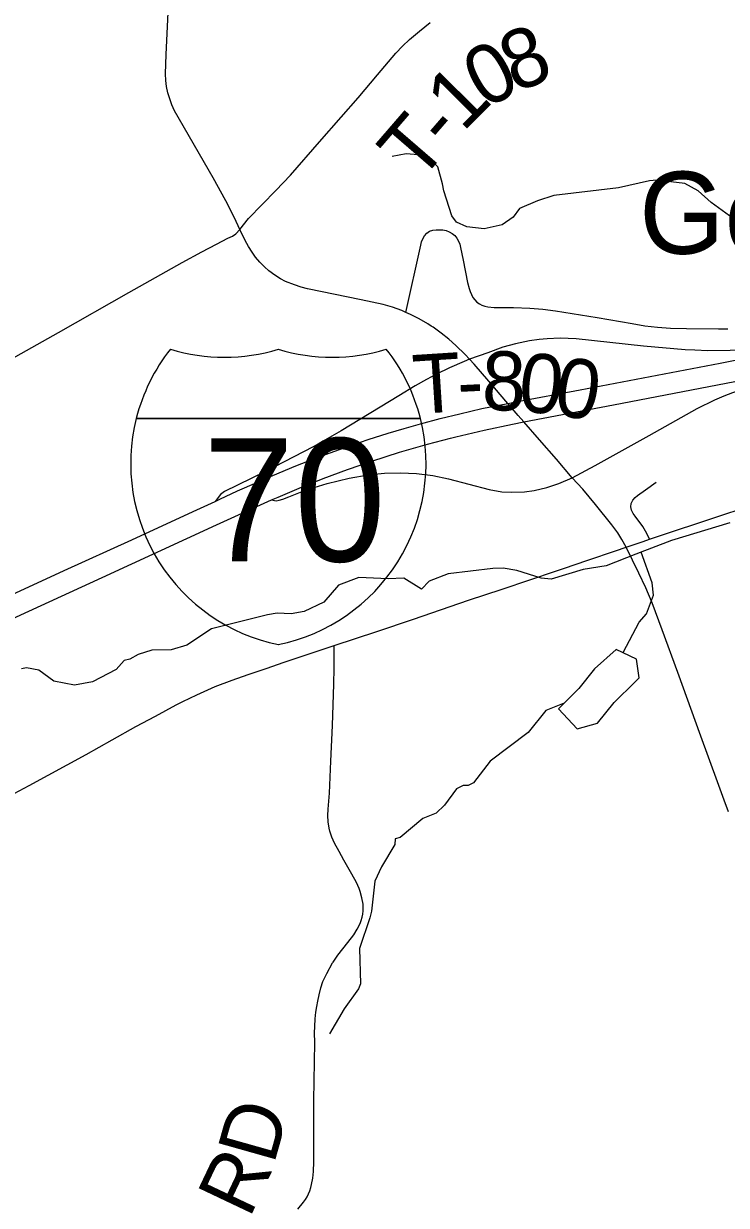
# Model space of a CAD drawing. Extents: x 0 to 34, y 0 to 22.
# Drawn here: x 5.879 to 6.555, y 16.504 to 17.641 of the extents above; entities that cross this region are included whole.
import ezdxf

# ---------------------------------------------------------------- set-up
doc = ezdxf.new("R2010")
doc.units = 0
for name, color, linetype in [('GM_X_County_Road', 7, 'Continuous'), ('GM_X_County_Road_Text', 7, 'Continuous'), ('GM_X_Interchange_Ramps', 7, 'Continuous'), ('GM_X_Interstate_Location', 7, 'Continuous'), ('GM_X_Interstate_Route', 7, 'Continuous'), ('GM_X_Interstate_Shield', 7, 'Continuous'), ('GM_X_Minor_Lake', 7, 'Continuous'), ('GM_X_Minor_River', 7, 'Continuous'), ('GM_X_Township_Road', 7, 'Continuous'), ('GM_X_Township_Road_Text', 7, 'Continuous'), ('GM_X_Unincorporated_Text', 7, 'Continuous'), ('GM_X_US_Route', 7, 'Continuous')]:
    doc.layers.add(name, color=color, linetype=linetype)

msp = doc.modelspace()

# ---------------------------------------------------------------- linework, layer by layer
at = {"layer": 'GM_X_County_Road'}
msp.add_line((6.5568, 16.8829), (6.5527, 16.8941), dxfattribs=at)
for points in [[(6.0868, 17.4429), (6.0816, 17.454), (6.0731, 17.4704), (6.061, 17.4925), (6.024, 17.5571), (6.0214, 17.5627), (6.0193, 17.5684), (6.0175, 17.5743), (6.0163, 17.5803), (6.0155, 17.5863), (6.0152, 17.5925), (6.0157, 17.6111), (6.0186, 17.672), (6.0235, 17.762)], [(5.6309, 17.1975), (5.6373, 17.2025), (5.6495, 17.2114), (5.6571, 17.2161), (5.6635, 17.2194), (5.6722, 17.2229), (5.7007, 17.2329), (5.7281, 17.2426), (5.7393, 17.247), (5.7476, 17.2511), (5.7585, 17.257), (5.7719, 17.2647), (5.8149, 17.2893), (5.8611, 17.3149), (5.9124, 17.3439), (5.9799, 17.3822), (6.0313, 17.4112), (6.0502, 17.4215), (6.0641, 17.4289), (6.0753, 17.4344), (6.0797, 17.4363), (6.0828, 17.4387), (6.0868, 17.4429)], [(6.2465, 17.3631), (6.2424, 17.3649), (6.2336, 17.3681), (6.2245, 17.3706), (6.2033, 17.3753), (6.1517, 17.3857), (6.1457, 17.3874), (6.1392, 17.3895), (6.1306, 17.3929), (6.1258, 17.3954), (6.1203, 17.3989), (6.1147, 17.4032), (6.1104, 17.4071), (6.1058, 17.4113), (6.1018, 17.4162), (6.0985, 17.4211), (6.0951, 17.4266), (6.0917, 17.4324), (6.0868, 17.4429)], [(6.2709, 17.35), (6.2675, 17.3522), (6.2593, 17.3568), (6.251, 17.3612), (6.2465, 17.3631)], [(6.3077, 17.3182), (6.3035, 17.3226), (6.2946, 17.3313), (6.2876, 17.3375), (6.2803, 17.3433), (6.2727, 17.3488), (6.2709, 17.35)], [(6.4063, 17.2039), (6.3914, 17.2219), (6.375, 17.2406), (6.3599, 17.2578), (6.3545, 17.2639), (6.3445, 17.2756), (6.3262, 17.297), (6.312, 17.3135), (6.3077, 17.3182)], [(6.4583, 17.1372), (6.4543, 17.1446), (6.4502, 17.1512), (6.4446, 17.1588), (6.4288, 17.1785), (6.4166, 17.193), (6.4063, 17.2039)], [(6.5527, 16.8941), (6.5462, 16.9118), (6.5302, 16.9555), (6.5081, 17.0169), (6.4931, 17.0577), (6.4832, 17.0838), (6.4772, 17.0982), (6.4705, 17.1122), (6.4583, 17.1372)], [(6.1764, 16.7384), (6.1811, 16.7451), (6.1906, 16.7572), (6.1962, 16.7646), (6.1996, 16.7699), (6.2024, 16.7754), (6.2035, 16.7784), (6.2044, 16.7814), (6.205, 16.7845), (6.2053, 16.7876), (6.2054, 16.7907), (6.2052, 16.7939), (6.2042, 16.8001), (6.2025, 16.8062), (6.2014, 16.8091), (6.1989, 16.8148), (6.1945, 16.823), (6.1868, 16.8365), (6.1821, 16.8446), (6.1778, 16.8527), (6.1753, 16.8584), (6.1733, 16.8642), (6.1726, 16.8671), (6.1717, 16.8732), (6.1715, 16.8793), (6.1718, 16.8855), (6.1728, 16.9009), (6.1735, 16.9163), (6.1742, 16.9317), (6.1758, 16.9657), (6.177, 17.0057), (6.1774, 17.0211), (6.1775, 17.0429)], [(6.1425, 16.5007), (6.148, 16.5074), (6.1498, 16.51), (6.1514, 16.5127), (6.1539, 16.5184), (6.1549, 16.5214), (6.1557, 16.5244), (6.1568, 16.5306), (6.1575, 16.5368), (6.1579, 16.5461), (6.1578, 16.5678), (6.1579, 16.5834), (6.1578, 16.6051), (6.1584, 16.6423), (6.1587, 16.6609), (6.1586, 16.6702), (6.1588, 16.6763), (6.1592, 16.6839), (6.1598, 16.6901), (6.1607, 16.6956), (6.1618, 16.7009), (6.1629, 16.7069), (6.1646, 16.7136), (6.1666, 16.7197), (6.1703, 16.7274), (6.1758, 16.7376), (6.1764, 16.7384)]]:
    msp.add_lwpolyline(points, dxfattribs=at)
at = {"layer": 'GM_X_Interchange_Ramps'}
for points in [[(6.638, 17.332), (6.6278, 17.3335), (6.6194, 17.3334), (6.5993, 17.3304), (6.5832, 17.3283), (6.5694, 17.327), (6.5585, 17.3265), (6.5368, 17.3262), (6.5244, 17.3268), (6.5151, 17.3271), (6.475, 17.3308), (6.4102, 17.3376), (6.3948, 17.3382), (6.3824, 17.3378), (6.3748, 17.3371), (6.3654, 17.3359), (6.3518, 17.333), (6.3398, 17.3297), (6.3253, 17.3243), (6.3077, 17.3182)], [(6.4063, 17.2039), (6.4286, 17.2158), (6.4804, 17.2447), (6.5267, 17.2707), (6.5435, 17.279), (6.5525, 17.283), (6.5608, 17.2861), (6.5786, 17.292), (6.6029, 17.2981), (6.6461, 17.3071), (6.6703, 17.312), (6.6778, 17.315), (6.6856, 17.3202)], [(6.3077, 17.3182), (6.3024, 17.3158), (6.2883, 17.3097), (6.276, 17.3038), (6.2662, 17.2985), (6.2554, 17.2925), (6.2395, 17.283), (6.1841, 17.2491), (6.1573, 17.2338), (6.1106, 17.2097), (6.0719, 17.191), (6.0682, 17.188), (6.063, 17.1814)], [(6.1173, 17.1828), (6.1216, 17.182), (6.1245, 17.1825), (6.1281, 17.1834), (6.1337, 17.1857), (6.1499, 17.1921), (6.1707, 17.1985), (6.1919, 17.2038), (6.2102, 17.2069), (6.2257, 17.2084), (6.2413, 17.2088), (6.2568, 17.2081), (6.2722, 17.2062), (6.2875, 17.2032), (6.3265, 17.1928), (6.3388, 17.1907), (6.3481, 17.1901), (6.3605, 17.1905), (6.3698, 17.1917), (6.3819, 17.1946), (6.3936, 17.1986), (6.4063, 17.2039)]]:
    msp.add_lwpolyline(points, dxfattribs=at)
at = {"layer": 'GM_X_Interstate_Route'}
for points in [[(6.4461, 17.2744), (6.5961, 17.303), (6.6856, 17.3202), (6.7151, 17.3259), (6.8371, 17.3495), (6.8976, 17.361)], [(6.063, 17.1814), (6.0673, 17.1834), (6.0846, 17.1914), (6.103, 17.1996), (6.1183, 17.2063), (6.1405, 17.2156), (6.1638, 17.2247), (6.1879, 17.2333), (6.2102, 17.2409), (6.2295, 17.2469), (6.2449, 17.2514), (6.2605, 17.2561), (6.2793, 17.2611), (6.2984, 17.2656), (6.3194, 17.2706), (6.3445, 17.2756), (6.3522, 17.2772), (6.4142, 17.2888), (6.5486, 17.3144), (6.638, 17.332)], [(6.2895, 17.2422), (6.2944, 17.2434), (6.3216, 17.2499), (6.349, 17.2557), (6.3599, 17.2578), (6.4344, 17.2721), (6.4461, 17.2744)], [(6.1173, 17.1828), (6.1236, 17.1855), (6.1438, 17.1942), (6.1669, 17.2035), (6.1902, 17.2121), (6.2137, 17.2202), (6.2404, 17.2286), (6.2673, 17.2363), (6.2895, 17.2422)], [(4.7609, 16.6592), (4.7838, 16.6653), (4.8529, 16.6836), (5.0932, 16.7471), (5.132, 16.758), (5.1647, 16.7679), (5.2061, 16.7812), (5.2414, 16.7931), (5.2823, 16.8079), (5.3288, 16.8255), (5.3663, 16.8405), (5.4006, 16.855), (5.4545, 16.879), (5.5249, 16.9113), (5.6013, 16.9464), (5.9542, 17.1082), (6.0643, 17.1589), (6.1173, 17.1828)], [(5.7653, 17.0446), (5.9177, 17.1148), (5.9827, 17.1444), (6.0419, 17.1717), (6.063, 17.1814)]]:
    msp.add_lwpolyline(points, dxfattribs=at)
at = {"layer": 'GM_X_Interstate_Shield'}
for p, q in [((5.9871, 17.2612), (6.2604, 17.2612)), ((6.2604, 17.2612), (5.9871, 17.2612)), ((6.2604, 17.2612), (5.9871, 17.2612))]:
    msp.add_line(p, q, dxfattribs=at)
for centre, start, end in [((6.1593, 17.2177), 141.669, 165.8066), ((6.0719, 17.4976), 253.0091, 286.9909), ((6.1756, 17.4976), 253.0091, 286.9909), ((6.0882, 17.2177), 14.1934, 38.331), ((6.1593, 17.2177), 165.8066, 258.463), ((6.0882, 17.2177), 281.537, 14.1934)]:
    msp.add_arc(centre, 0.1776, start, end, dxfattribs=at)
at = {"layer": 'GM_X_Minor_Lake'}
for points in [[(6.4709, 17.0118), (6.4683, 17.0296), (6.4486, 17.0391), (6.4278, 17.0205), (6.4127, 17.0015), (6.3934, 16.9818)], [(6.4709, 17.0118), (6.4683, 17.0296), (6.4486, 17.0391), (6.4278, 17.0205), (6.4127, 17.0015), (6.3934, 16.9818), (6.4111, 16.9625), (6.4308, 16.9681), (6.4467, 16.9879), (6.4671, 17.008), (6.4709, 17.0118)], [(6.3934, 16.9818), (6.4111, 16.9625), (6.4308, 16.9681), (6.4467, 16.9879), (6.4671, 17.008), (6.4709, 17.0118)]]:
    msp.add_lwpolyline(points, dxfattribs=at)
at = {"layer": 'GM_X_Minor_River'}
for points in [[(6.5682, 17.4483), (6.5402, 17.4687), (6.5276, 17.48), (6.5147, 17.4872), (6.4878, 17.4904), (6.4807, 17.4896), (6.4508, 17.483), (6.3888, 17.4755), (6.3729, 17.4705), (6.3556, 17.4631), (6.3496, 17.4548), (6.339, 17.4475), (6.3216, 17.4436), (6.305, 17.4454), (6.2951, 17.4499), (6.2906, 17.456), (6.2829, 17.4802), (6.2817, 17.4867), (6.2771, 17.503), (6.2725, 17.5083), (6.2581, 17.5146), (6.2468, 17.5157), (6.2331, 17.513)], [(6.5579, 17.1609), (6.502, 17.1439), (6.4677, 17.1305), (6.439, 17.1193), (6.4171, 17.1158), (6.3861, 17.1065), (6.3766, 17.1076), (6.3531, 17.115), (6.3399, 17.1173), (6.3301, 17.1168), (6.287, 17.1117), (6.2688, 17.1047), (6.2613, 17.0971), (6.2446, 17.1076), (6.2295, 17.1068), (6.2011, 17.1082), (6.1815, 17.1008), (6.1676, 17.0844), (6.1487, 17.0756), (6.1362, 17.0733), (6.1226, 17.0739), (6.1132, 17.0724), (6.0595, 17.0588), (6.0358, 17.0431), (6.0206, 17.0385), (6.0021, 17.0384), (5.9889, 17.0341), (5.981, 17.0295), (5.9753, 17.0284), (5.9678, 17.0196), (5.9451, 17.0077), (5.9278, 17.0046), (5.9077, 17.0086), (5.8933, 17.0192), (5.8815, 17.0214), (5.8766, 17.0202)], [(6.4553, 17.0359), (6.471, 17.0652), (6.4778, 17.0732), (6.4845, 17.0911), (6.4833, 17.1032), (6.4729, 17.1325)], [(6.3986, 16.9872), (6.3811, 16.9804), (6.3641, 16.9591), (6.3276, 16.9316), (6.3114, 16.9106), (6.3065, 16.9083), (6.3016, 16.9083), (6.2952, 16.9048), (6.2835, 16.8892), (6.2756, 16.8816), (6.2628, 16.8765), (6.2409, 16.8582), (6.236, 16.8567), (6.2357, 16.8513), (6.2229, 16.83), (6.2166, 16.8163), (6.2133, 16.7874), (6.2118, 16.781), (6.2018, 16.7513), (6.2027, 16.7175), (6.2008, 16.7126), (6.1869, 16.6935), (6.173, 16.6692)]]:
    msp.add_lwpolyline(points, dxfattribs=at)
at = {"layer": 'GM_X_Township_Road'}
for points in [[(6.0868, 17.4429), (6.0951, 17.4535), (6.1214, 17.4803), (6.1353, 17.4952), (6.1634, 17.5271), (6.1842, 17.5509), (6.2006, 17.5696), (6.2191, 17.5916), (6.2369, 17.6123), (6.2433, 17.6191), (6.25, 17.6256), (6.2595, 17.6337), (6.2698, 17.6418)], [(6.2465, 17.3631), (6.2608, 17.4278), (6.2616, 17.4309), (6.2628, 17.4339), (6.2643, 17.4367), (6.2665, 17.4392), (6.2692, 17.4411), (6.2722, 17.4423), (6.2755, 17.4427), (6.2788, 17.4427), (6.282, 17.4424), (6.2851, 17.4418), (6.2882, 17.4407), (6.291, 17.4391), (6.2935, 17.437), (6.2955, 17.4345), (6.2971, 17.4317), (6.2983, 17.4287), (6.2991, 17.4256), (6.3016, 17.4133), (6.3057, 17.3919), (6.3073, 17.386), (6.3083, 17.3831), (6.3095, 17.3803), (6.3109, 17.3776), (6.3127, 17.3752), (6.3147, 17.3731), (6.3171, 17.3714), (6.3196, 17.3701), (6.3224, 17.3691), (6.3253, 17.3685), (6.3313, 17.368), (6.3501, 17.368), (6.3656, 17.3673), (6.3781, 17.3662), (6.3904, 17.3646), (6.4304, 17.3581), (6.4641, 17.3523), (6.4763, 17.3502), (6.4886, 17.3488), (6.501, 17.348), (6.5165, 17.3476), (6.5472, 17.3473), (6.5562, 17.3473)], [(6.4809, 17.1449), (6.4783, 17.1505), (6.4745, 17.1572), (6.4669, 17.1671), (6.4651, 17.1698), (6.4636, 17.1728), (6.4629, 17.1761), (6.4633, 17.1794), (6.4648, 17.1824), (6.4669, 17.185), (6.4693, 17.1871), (6.477, 17.1926), (6.4873, 17.1998)]]:
    msp.add_lwpolyline(points, dxfattribs=at)
at = {"layer": 'GM_X_US_Route'}
for points in [[(6.4809, 17.1449), (6.5513, 17.1683), (6.5689, 17.1742), (6.593, 17.1821)], [(6.4583, 17.1372), (6.4746, 17.1428), (6.4809, 17.1449)], [(6.3904, 17.1143), (6.3981, 17.1169), (6.4216, 17.1248), (6.4481, 17.1337), (6.4583, 17.1372)], [(6.1775, 17.0429), (6.2185, 17.0563), (6.2538, 17.0682), (6.3067, 17.0863), (6.3392, 17.097), (6.3657, 17.1059), (6.3904, 17.1143)], [(6.0317, 16.9888), (6.0453, 16.9955), (6.0629, 17.0032), (6.0793, 17.0094), (6.0946, 17.0148), (6.1131, 17.0211), (6.1283, 17.0263), (6.1494, 17.0334), (6.1649, 17.0386), (6.1775, 17.0429)], [(5.6904, 16.8287), (5.7932, 16.8674), (5.814, 16.8757), (5.8308, 16.8826), (5.8479, 16.8899), (5.8647, 16.898), (5.8839, 16.9083), (5.9388, 16.9379), (5.9639, 16.9522), (5.9866, 16.9648), (6.0056, 16.9748), (6.0254, 16.9856), (6.0317, 16.9888)]]:
    msp.add_lwpolyline(points, dxfattribs=at)

# ---------------------------------------------------------------- texts
at = {"layer": 'GM_X_County_Road_Text'}
for s, rotation, p in [('D', 74.2623, (6.1193, 16.5427)), ('R', 64.6377, (6.0958, 16.4909))]:
    msp.add_text(s, height=0.0568, rotation=rotation, dxfattribs=at).set_placement(p)
at = {"layer": 'GM_X_Interstate_Location'}
for s in ['.', '-', ',']:
    msp.add_text(s, height=0.000189, dxfattribs=at).set_placement((6.1237, 17.1857))
msp.add_text('70', height=0.000189, rotation=0, dxfattribs=at).set_placement((6.085, 17.1465))
at = {"layer": 'GM_X_Interstate_Shield'}
msp.add_text('70', height=0.11837, dxfattribs=at).set_placement((6.051, 17.1236))
at = {"layer": 'GM_X_Township_Road_Text'}
for s, rotation, p in [('8', 21.8517, (6.3515, 17.574)), ('0', 28.6321, (6.3224, 17.558)), ('1', 45.3165, (6.3012, 17.5358)), ('T', 49.1886, (6.2589, 17.4867)), ('-', 49.027, (6.2866, 17.5189)), ('T', 3.6453, (6.2548, 17.2653)), ('8', 359.313, (6.3193, 17.2691)), ('0', 353.9207, (6.3529, 17.2687)), ('0', 351.1075, (6.387, 17.2651)), ('-', 2.7879, (6.2969, 17.2679))]:
    msp.add_text(s, height=0.0568, rotation=rotation, dxfattribs=at).set_placement(p)
at = {"layer": 'GM_X_Unincorporated_Text'}
msp.add_text('Georgetown', height=0.07898, rotation=0, dxfattribs=at).set_placement((6.4709, 17.4195))

doc.saveas('drawing.dxf')
